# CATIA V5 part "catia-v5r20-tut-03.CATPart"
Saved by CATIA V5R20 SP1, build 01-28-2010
Part number: c03tut3
Bounding box of the stored display mesh (mm): x 0 to 0, y -100 to 100, z 0 to 90
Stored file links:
  D:\v5_r20\psrt_files_downloaded\c03-catia-v5r20-prt\catia-v5r20-tut-03.CATPart
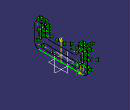
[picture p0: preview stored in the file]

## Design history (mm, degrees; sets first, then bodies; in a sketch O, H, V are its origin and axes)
Body1 (main body)
  Sketch1 on yz-plane, origin (0, 0, 0), H (0, 1, 0), V (0, 0, 1)
    line L1 (0, 0) -> (85, 0)
    line L2 (100, 15) -> (100, 80)
    line L3 (90, 90) -> (70, 90)
    line L4 (60, 80) -> (60, 60)
    line L5 (50, 50) -> (0, 50)
    point P1 (0, 50)
    arc A1 centre (85, 15) radius 15 from (85, 0) to (100, 15) ccw
    point P2 (85, 0)
    point P3 (100, 15)
    arc A2 centre (50, 60) radius 10 from (60, 60) to (50, 50) cw
    point P5 (60, 60)
    point P6 (50, 50)
    arc A3 centre (70, 80) radius 10 from (70, 90) to (60, 80) ccw
    point P8 (70, 90)
    point P9 (60, 80)
    arc A4 centre (90, 80) radius 10 from (100, 80) to (90, 90) ccw
    point P11 (100, 80)
    point P12 (90, 90)
    construction line L6 (80, 70) -> (80, 40)
    line L7 (85, 70) -> (85, 40)
    line L8 (75, 40) -> (75, 70)
    arc A5 centre (80, 40) radius 5 from (85, 40) to (75, 40) cw
    arc A6 centre (80, 70) radius 5 from (75, 70) to (85, 70) cw
    point P16 (85, 70)
    point P17 (85, 40)
    point P18 (75, 40)
    point P19 (75, 70)
    point P20 (0, 0)
    point P21 (0, 50)
    point P22 (-85, 0)
    point P23 (-100, 15)
    point P25 (-60, 60)
    point P26 (-50, 50)
    point P28 (-70, 90)
    point P29 (-60, 80)
    point P31 (-100, 80)
    point P32 (-90, 90)
    construction line L9 (-80, 70) -> (-80, 40)
    point P36 (-85, 70)
    point P37 (-85, 40)
    point P38 (-75, 40)
    point P39 (-75, 70)
    line L10 (0, 0) -> (-85, 0)
    line L11 (-100, 15) -> (-100, 80)
    line L12 (-90, 90) -> (-70, 90)
    line L13 (-60, 80) -> (-60, 60)
    line L14 (-50, 50) -> (0, 50)
    arc A7 centre (-85, 15) radius 15 from (-85, 0) to (-100, 15) cw
    arc A8 centre (-50, 60) radius 10 from (-60, 60) to (-50, 50) ccw
    arc A9 centre (-70, 80) radius 10 from (-70, 90) to (-60, 80) cw
    arc A10 centre (-90, 80) radius 10 from (-100, 80) to (-90, 90) cw
    line L15 (-85, 70) -> (-85, 40)
    line L16 (-75, 40) -> (-75, 70)
    arc A11 centre (-80, 40) radius 5 from (-85, 40) to (-75, 40) ccw
    arc A12 centre (-80, 70) radius 5 from (-75, 70) to (-85, 70) ccw
    construction line L17 (60, 20) -> (-60, 20)
    point P40 (60, 20)
    line L18 (60, 10) -> (-60, 10)
    line L19 (-60, 30) -> (60, 30)
    arc A13 centre (-60, 20) radius 10 from (-60, 10) to (-60, 30) cw
    arc A14 centre (60, 20) radius 10 from (60, 30) to (60, 10) cw
    radius A1 = 15
    radius A2 = 10
    radius A3 = 10
    radius A4 = 10
    distance L6 L7 = 5
    distance L17 L18 = 10
    horizontal: L1 H, L3 H, L5 H, L17 H
    vertical: L2 V, L4 V
    coincidence: P1 V, P40 L4
    tangency: A1 L1, A1 L2, A2 L4, A2 L5, A3 L3, A3 L4, A4 L2, A4 L3, L6 A3, A5 L7, A6 L7, A5 L8, A6 L8, A13 L18, A14 L18, A13 L19, A14 L19
    symmetry: O P20 V, P1 P21 V, P2 P22 V, P3 P23 V, P5 P25 V, P6 P26 V, P8 P28 V, P9 P29 V, P11 P31 V, P12 P32 V, L6 L9 V, P16 P36 V, P17 P37 V, P18 P38 V, P19 P39 V, L1 L10 V, L2 L11 V, L3 L12 V, L4 L13 V, L5 L14 V, A1 A7 V, A2 A8 V, A3 A9 V, A4 A10 V, L7 L15 V, L8 L16 V, A5 A11 V, A6 A12 V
